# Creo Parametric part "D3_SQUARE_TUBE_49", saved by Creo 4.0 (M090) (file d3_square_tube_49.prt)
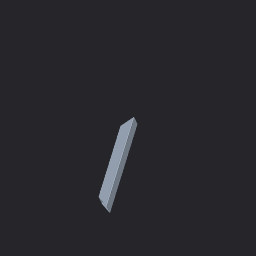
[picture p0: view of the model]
Units: Custom; MM, KILOGRAM, SECS
Materials in the file: STEEL

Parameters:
  BUW_NAME = "SQUARE TUBE"
  BUW_TYPE = "DIN EN 10210"
  BUW_SIZE = "60x60x3.0"
  BUW_LENGTH_STR = "560"
  PTC_MATERIAL_NAME = "STEEL"
  BUW_PROFIL_TYPE = "square_tube"
  BUW_PROFILE_PATH = "parts/profiles/steel_beams_mm/"
  BUW_PROFILE_NAME_LANG = "SQUARE TUBE"
  BUW_TAB_SEL_INFO = "2  0 2  3 19"
  MITRE_SYM_X_S = "|"
  MITRE_SYM_X_E = "|"
  MITRE_SYM_X = "|---|"
  MITRE_SYM_Y_S = "\"
  MITRE_SYM_Y_E = "/"
  MITRE_SYM_Y = "\---/"
  MITRE_BOM_Y = "Y \---/"
  BUW_DOUBLE_TO_STR_INFO = "X_ROT_S2 2 X_ROT_E2 2 Y_ROT_S2 2 Y_ROT_E2 2"
  X_ROT_S2_STR = "90"
  X_ROT_E2_STR = "90"
  Y_ROT_S2_STR = "45"
  Y_ROT_E2_STR = "45"
  BOM_ANGLE_S = "Y 45°"
  BOM_ANGLE_E = "Y 45°"
  EFX_ITEM_NR = "2"
  PROFIL_RASTER_POS = "X_0"
  BUW_OBJECT_ROLE = "PROFIL_SYSTEM_BORE_END_POINTS"
  PRO_UNIT_SYS = "Custom"

Other parameters: BUW_LENGTH, X_ROT_S2, X_ROT_E2, Y_ROT_S2, Y_ROT_E2, D8, D93, D94, d26, d8, d93, d94, d98, D98, D0, D4, D1, D5, SHEAR_MODULUS, THERM_EXPANSION_REF_TEMPERATURE, STRUCTURAL_DAMPING_COEFFICIENT, STRESS_LIMIT_FOR_TENSION, STRESS_LIMIT_FOR_COMPRESSION, STRESS_LIMIT_FOR_SHEAR, EMISSIVITY

Created from: SQUARE_TUBE.PRT

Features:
  1. datum plane "YZ"
  2. datum plane "XZ"
  3. datum plane "XY"
  4. coordinate system
  5. coordinate system
  6. coordinate system
  7. coordinate system
  8. datum plane "DTM3"
  9. datum plane "DTM4"
  10. datum plane "DTM5"
  11. protrusion
  12. round
  13. round
  14. datum axis
  15. datum point "PNT0"
  16. datum point

Other named items: PROFIL_CUT_QUILT, PROFILE_LENGTH_DIM, CONTACT_SURF_3, CONTACT_SURF_2, CONTACT_SURF_1, CONTACT_SURF_0, E, START_SURFACE, END_SURFACE, SIDE_SURF_3, SIDE_SURF_0, SIDE_SURF_1, SIDE_SURF_2, EDGE_7_S, EDGE_7_E, EDGE_1_S, EDGE_1_E, EDGE_3_S, EDGE_3_E, EDGE_5_S, EDGE_5_E, EDGE_6_S, EDGE_4_S, EDGE_2_S, EDGE_0_S, EDGE_6_E, EDGE_4_E, EDGE_2_E, EDGE_0_E, CS0, CS_S, CS_E, CS3

Named dimensions: X_ROT_S, Y_ROT_S, Z_OFF_S, X_ROT_E, Y_ROT_E, Z_OFF_E, PC_L, BUW_LENGTH_Z_MIN, BUW_LENGTH_DIM

Layers: 00_PROFIL_DATUM, 00_PROFIL_DRW_HIDE, 00_PROFIL_END_CSYS, 00_PROFIL_GEOMETRY, 00_PROFIL_QUILT, 00_PROFIL_SIZE_NOTE

Surfaces: 10 plane, 8 cylinder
